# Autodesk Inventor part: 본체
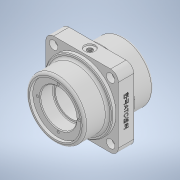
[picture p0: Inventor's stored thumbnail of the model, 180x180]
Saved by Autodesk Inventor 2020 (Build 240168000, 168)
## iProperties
Created: 2023-10
Part Number: 본체
Material: 일반
Document SubType Name: Modeling
Designer: oem
Density: 1 g/cm^3
Appearance: 기본값
Author: oem
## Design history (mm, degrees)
sketch "스케치1"
  geometry: L1 (-47, -47)-(47, -47); L2 (47, -47)-(47, 47); L3 (47, 47)-(-47, 47); L4 (-47, 47)-(-47, -47); L5 (-47, -47)-(47, 47); L6 (47, -47)-(-47, 47); 1 further point
  constraints: 12 end point, 2 midpoint, 2 parallel, 1 horizontal, 1 perpendicular
  dimensions: "d0" = 94 distance between parallel lines of L1 L3; "d1" = 94 distance between parallel lines of L2 L4
extrude "돌출1" new body sketch "스케치1" stored distance "d2" = 20; taper "d3" = 0 deg
sketch "스케치2"
  geometry: C1 r 44 at (0, 0); 1 further point
  constraints: 1 centre point, 1 coincident
  dimensions: "d4" = 88 diameter of C1
extrude "돌출2" join sketch "스케치2" distance "d5" = 5; taper "d6" = 0 deg
sketch "스케치3"
  geometry: C1 r 44 at (0, 0) reference; C2 r 38 at (0, 0)
  constraints: 1 centre point, 1 coincident
  dimensions: "d7" = 76 diameter of C2
extrude "돌출3" join sketch "스케치3" distance "d8" = 30; taper "d9" = 0 deg
node "작업 평면1"
sketch "스케치4"
  geometry: L1 (38, 45)-(-38, 45) reference; L2 (0, 45)-(0, -45); L3 (38, -45)-(-38, -45) reference; L4 (0, 45)-(33, 45); L5 (33, 45)-(33, 41); L6 (33, 41)-(23.5, 41); L7 (23.5, 41)-(23.5, 24); L8 (23.5, 24)-(20.5, 24); L9 (20.5, 24)-(20.5, -24); L10 (-47, -10)-(47, -10) reference; L11 (20.5, -24)-(23.5, -24); L12 (23.5, -24)-(23.5, -41); L13 (23.5, -41)-(33, -41); L14 (33, -41)-(33, -45); 3 further points
  constraints: 22 end point, 6 perpendicular, 6 point on line, 2 midpoint, 1 vertical
  dimensions: "d11" = 66 diameter of L5 L2; "d12" = 47 diameter of L7 L2; "d13" = 41 diameter of L9 L2; "d14" = 4 distance between parallel lines of L6 L4; "d15" = 17 distance between parallel lines of L8 L6; "d16" = 4 distance between parallel lines of L3 L13; "d17" = 17 distance between parallel lines of L13 L11
revolve "회전1" sketch "스케치4" stored, may be unused: angle "d18" = 90 deg
sketch "스케치5"
  geometry: C1 r 33 at (0, 0) reference; 1 further point
  constraints: 1 vertical alignment
  dimensions: "d19" = 27 distance of point (0, 27) C1.centre
hole "구멍1" sketch "스케치5" at (0, 27) diameter "d20" = 3.242; stored, may be unused: countersink angle "d24" = 90 deg, drill point angle "d26" = 118 deg; dims "d21" = 8, "d22" = 18, "d23" = 2, "d25" = 10
fillet "모깎기1" dims "d30" = 10
fillet "모깎기2" dims "d31" = 10
sketch "스케치7"
  geometry: A1 r 10 centre (-37, -37) between (-47, -37) and (-37, -47) reference; A2 r 10 centre (37, -37) between (37, -47) and (47, -37) reference; A3 r 10 centre (37, 37) between (47, 37) and (37, 47) reference; A4 r 10 centre (-37, 37) between (-37, 47) and (-47, 37) reference; 4 further points
  constraints: 4 coincident
hole "구멍2" sketch "스케치7" at (-37, 37), (37, 37), (37, -37), (-37, -37) diameter "d32" = 6.6; stored, may be unused: countersink angle "d36" = 90 deg, drill point angle "d38" = 118 deg; dims "d33" = 8, "d34" = 11, "d35" = 7, "d37" = 10
sketch "스케치8"
  geometry: C1 r 3.3 at (-37, 37) reference; A1 r 10 centre (37, -37) between (37, -47) and (47, -37) reference; A2 r 10 centre (37, 37) between (47, 37) and (37, 47) reference; A3 r 10 centre (-37, -37) between (-47, -37) and (-37, -47) reference; 4 further points
  constraints: 4 coincident
hole "구멍3" sketch "스케치8" at (37, 37), (-37, 37), (-37, -37), (37, -37) diameter "d39" = 6.6; stored, may be unused: countersink angle "d43" = 90 deg, drill point angle "d45" = 118 deg; dims "d40" = 8, "d41" = 11, "d42" = 7, "d44" = 10
node "작업 평면2"
sketch "스케치9"
  geometry: 2 further points
  constraints: 1 coincident, 1 other
feature "엠보싱1" sketch "스케치9" dims "d0" = 94, "d1" = 94, "d47" = 0.5, "d48" = 0
sketch "스케치10"
  geometry: 2 further points
  constraints: 1 coincident
hole "구멍4" sketch "스케치10" at (37, 10) diameter "d49" = 7; stored, may be unused: countersink angle "d53" = 90 deg, drill point angle "d55" = 0 deg; dims "d50" = 8, "d51" = 14, "d52" = 2, "d54" = 4
sketch "스케치13"
  geometry: C1 r 3.5 at (0, 0) reference; 1 further point
  constraints: 1 coincident
hole "구멍6" sketch "스케치13" at (0, 0) diameter "d63" = 5.1881; stored, may be unused: countersink angle "d67" = 90 deg, drill point angle "d69" = 0 deg; dims "d64" = 12, "d65" = 7, "d66" = 2, "d68" = 16
chamfer "모따기1" distance "d77" = 1; stored, may be unused: second distance "d78" = 2, angle "d79" = 45 deg
fillet "모깎기3" dims "d80" = 1
fillet "모깎기4" dims "d81" = 3
node "솔리드1"
mirror "미러1"
pattern_circular "원형 패턴1" dims angle "d28" = 360 deg
mirror "미러2"
feature "A9D066F2-1C7D-4E18-AEED-F7BC21143FA4" dims "d32" = 6.6, "d33" = 8, "d34" = 11, "d35" = 7, "d36" = 90 deg, "d37" = 10, "d38" = 118 deg
other parameters: "d10" = 0, "d46" = 164.5
